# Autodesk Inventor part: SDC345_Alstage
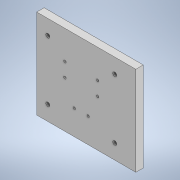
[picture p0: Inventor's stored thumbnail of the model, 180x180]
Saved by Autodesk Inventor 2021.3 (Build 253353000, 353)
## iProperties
Created: 2022-01
Part Number: SDC345_Alstage
Material: 一般
Document SubType Name: Modeling
Designer: kengo
Density: 1 g/cm^3
Appearance: 既定
Author: kengo
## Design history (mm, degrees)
sketch "スケッチ1"
  geometry: L1 (-97.411, 111.58)-(102.589, 111.58); L2 (102.589, 111.58)-(102.589, -68.42); L3 (102.589, -68.42)-(-97.411, -68.42); L4 (-97.411, -68.42)-(-97.411, 111.58); 1 further point
  constraints: 8 end point, 2 parallel, 1 horizontal, 1 perpendicular
  dimensions: "d0" = 200 distance of L1.start L1.end; "d1" = 180 distance of L1.end L2.end
extrude "押し出し1" new body sketch "スケッチ1" distance "d2" = 15; taper "d3" = 0 deg
sketch "スケッチ3"
  geometry: L1 (97.411, 111.58)-(97.411, -68.42) reference; L2 (97.411, -68.42)-(-102.589, -68.42) reference; L3 (-102.589, 111.58)-(97.411, 111.58) reference; L4 (-102.589, -68.42)-(-102.589, 111.58) reference; 2 further points
  dimensions: "d21" = 42.5 distance from line of L4 point (-60.089, 81.58); "d24" = 30 distance from line of L3 point (-60.089, 81.58)
hole "穴2" sketch "スケッチ3" at (-60.089, 81.58) diameter "d25" = 8; stored, may be unused: countersink angle "d29" = 90 deg, drill point angle "d31" = 118 deg; dims "d26" = 6, "d27" = 12, "d28" = 9, "d30" = 51.2
sketch "スケッチ4"
  geometry: L1 (-102.589, -68.42)-(-102.589, 111.58) reference; L2 (97.411, 111.58)-(97.411, -68.42) reference; L3 (-102.589, 111.58)-(97.411, 111.58) reference; 5 further points
  dimensions: "d32" = 77 distance from line of L1 point (-25.589, 53.58); "d33" = 77 distance from line of L1 point (-25.589, 25.58); "d34" = 57 distance from line of L2 point (40.411, 53.58); "d35" = 57 distance from line of L2 point (40.411, 25.58); "d36" = 28 distance of point (-25.589, 25.58) point (-25.589, 53.58); "d37" = 28 distance of point (40.411, 25.58) point (40.411, 53.58); "d38" = 58 distance from line of L3 point (40.411, 53.58); "d39" = 58 distance from line of L3 point (-25.589, 53.58)
hole "穴3" sketch "スケッチ4" at (-25.589, 53.58), (-25.589, 25.58), (40.411, 25.58), (40.411, 53.58) diameter "d40" = 4.917; stored, may be unused: countersink angle "d44" = 90 deg, drill point angle "d46" = 0 deg; dims "d41" = 12, "d42" = 4, "d43" = 2, "d45" = 10
sketch "スケッチ6"
  geometry: L1 (97.411, 111.58)-(97.411, -68.42) reference; L2 (97.411, -68.42)-(-102.589, -68.42) reference; C1 r 2.458 at (40.411, 25.58) reference; C2 r 2.458 at (-25.589, 25.58) reference; 3 further points
  dimensions: "d58" = 28 distance of point (21.411, -18.42) point (-6.589, -18.42); "d60" = 44 vertical distance of C1.centre point (21.411, -18.42); "d61" = 19 horizontal distance of C2.centre point (-6.589, -18.42); "d62" = 19 horizontal distance of C1.centre point (21.411, -18.42); "d63" = 50 distance from line of L2 point (21.411, -18.42) (derived)
hole "穴5" sketch "スケッチ6" at (-6.589, -18.42), (21.411, -18.42) diameter "d64" = 4.917; stored, may be unused: countersink angle "d68" = 90 deg, drill point angle "d70" = 0 deg; dims "d65" = 12, "d66" = 4, "d67" = 2, "d69" = 10
sketch "スケッチ7"
  geometry: L1 (97.411, -68.42)-(-102.589, -68.42) reference; L2 (-102.589, -68.42)-(-102.589, 111.58) reference; L3 (97.411, 111.58)-(97.411, -68.42) reference; L4 (-102.589, 111.58)-(97.411, 111.58) reference; 4 further points
  dimensions: "d74" = 30 distance from line of L1 point (-60.089, -38.42); "d75" = 42.5 distance from line of L2 point (-60.089, -38.42); "d76" = 22.5 distance from line of L3 point (74.911, -38.42); "d77" = 30 distance from line of L1 point (74.911, -38.42); "d78" = 22.5 distance from line of L3 point (74.911, 81.58); "d79" = 30 distance from line of L4 point (74.911, 81.58)
hole "穴6" sketch "スケッチ7" at (-60.089, -38.42), (74.911, -38.42), (74.911, 81.58) diameter "d80" = 8; stored, may be unused: countersink angle "d84" = 90 deg, drill point angle "d86" = 0 deg; dims "d81" = 10, "d82" = 4, "d83" = 2, "d85" = 22.2
node "ソリッド1"
